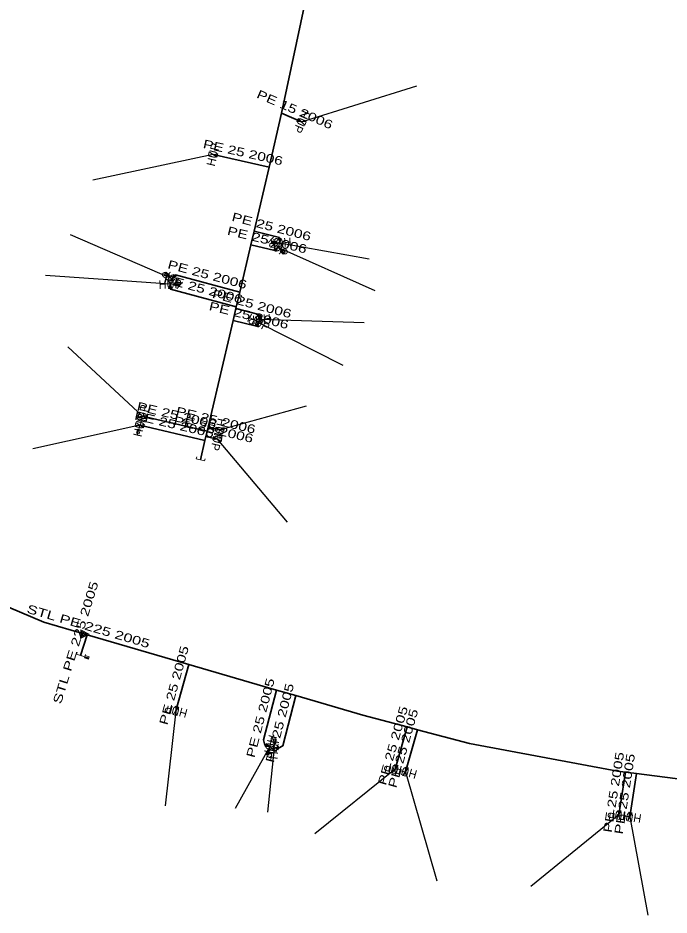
# Model space of a CAD drawing. Extents: x -737484 to -734496, y -1033882 to -1030666.
# Drawn here: x -736493.3 to -736417.8, y -1030969.6 to -1030865.6 of the extents above; entities that cross this region are included whole.
import ezdxf
from ezdxf.enums import TextEntityAlignment as Align

# ---------------------------------------------------------------- set-up
doc = ezdxf.new("R2010")
doc.units = 0
doc.header["$LTSCALE"] = 0.4
for name, color, linetype, lineweight in [('1', 7, 'Continuous', 13), ('22', 7, 'Continuous', 25), ('5', 7, 'Continuous', 35), ('7', 7, 'Continuous', 35)]:
    doc.layers.add(name, color=color, linetype=linetype, lineweight=lineweight)
doc.layers.add('2', color=7, linetype='Continuous')

msp = doc.modelspace()

# ---------------------------------------------------------------- linework, layer by layer
at = {"layer": '1'}
for p, q in [((-736463.478, -1030891.525), (-736463.827, -1030891.5)), ((-736462.91, -1030891.64), (-736463.408, -1030891.605)), ((-736463.14, -1030892.14), (-736462.78, -1030892.487)), ((-736462.778, -1030892.593), (-736462.526, -1030892.836)), ((-736475.822, -1030895.392), (-736476.09, -1030895.167)), ((-736475.43, -1030895.82), (-736475.813, -1030895.498)), ((-736475.64, -1030896.44), (-736475.14, -1030896.422)), ((-736475.062, -1030896.494), (-736474.712, -1030896.482)), ((-736479.372, -1030913.333), (-736479.451, -1030913.674)), ((-736479.17, -1030912.79), (-736479.282, -1030913.277)), ((-736486.03, -1030939.49), (-736485.551, -1030939.636)), ((-736485.502, -1030939.729), (-736485.167, -1030939.832)), ((-736464.07, -1030950.05), (-736464.207, -1030950.53)), ((-736463.58, -1030950.19), (-736463.536, -1030949.691)), ((-736463.455, -1030949.623), (-736463.424, -1030949.275)), ((-736464.3, -1030950.582), (-736464.397, -1030950.918))]:
    msp.add_line(p, q, dxfattribs=at)
for points in [[(-736459.871, -1030877.611), (-736460.027, -1030877.979), (-736460.792, -1030877.22), (-736460.948, -1030877.588)], [(-736471.192, -1030881.492), (-736471.102, -1030881.102), (-736470.217, -1030881.717), (-736470.127, -1030881.327)], [(-736463.907, -1030891.57), (-736463.918, -1030891.719), (-736463.419, -1030891.754), (-736463.408, -1030891.605)], [(-736463.907, -1030891.57), (-736463.897, -1030891.42), (-736463.398, -1030891.455), (-736463.408, -1030891.605)], [(-736463.867, -1030891.535), (-736463.861, -1030891.461), (-736463.437, -1030891.49), (-736463.443, -1030891.565)], [(-736462.936, -1030891.641), (-736462.648, -1030891.919), (-736463.631, -1030892.36), (-736463.343, -1030892.638)], [(-736462.667, -1030892.12), (-736463.065, -1030892.155), (-736462.754, -1030891.124), (-736463.152, -1030891.159)], [(-736462.42, -1030892.834), (-736462.524, -1030892.942), (-736462.884, -1030892.595), (-736462.78, -1030892.487)], [(-736462.473, -1030892.834), (-736462.525, -1030892.888), (-736462.831, -1030892.593), (-736462.779, -1030892.539)], [(-736462.42, -1030892.834), (-736462.316, -1030892.726), (-736462.676, -1030892.379), (-736462.78, -1030892.487)], [(-736476.196, -1030895.177), (-736476.099, -1030895.062), (-736475.716, -1030895.383), (-736475.813, -1030895.498)], [(-736476.196, -1030895.177), (-736476.292, -1030895.292), (-736475.909, -1030895.613), (-736475.813, -1030895.498)], [(-736476.143, -1030895.173), (-736476.094, -1030895.115), (-736475.769, -1030895.389), (-736475.817, -1030895.446)], [(-736475.598, -1030896.331), (-736475.904, -1030896.074), (-736474.955, -1030895.565), (-736475.261, -1030895.308)], [(-736475.857, -1030895.947), (-736475.457, -1030895.933), (-736475.822, -1030896.946), (-736475.422, -1030896.932)], [(-736474.64, -1030896.405), (-736474.645, -1030896.255), (-736475.145, -1030896.272), (-736475.14, -1030896.422)], [(-736474.64, -1030896.405), (-736474.635, -1030896.555), (-736475.135, -1030896.572), (-736475.14, -1030896.422)], [(-736474.677, -1030896.443), (-736474.674, -1030896.518), (-736475.099, -1030896.533), (-736475.102, -1030896.458)], [(-736465.038, -1030900.986), (-736465.436, -1030901.028), (-736465.143, -1030899.991), (-736465.541, -1030900.033)], [(-736465.331, -1030900.354), (-736464.978, -1030900.542), (-736465.801, -1030901.237), (-736465.448, -1030901.425)], [(-736479.372, -1030911.812), (-736479.282, -1030911.422), (-736478.397, -1030912.037), (-736478.307, -1030911.647)], [(-736479.702, -1030912.872), (-736479.612, -1030912.482), (-736478.727, -1030913.097), (-736478.637, -1030912.707)], [(-736479.394, -1030913.764), (-736479.541, -1030913.73), (-736479.428, -1030913.243), (-736479.282, -1030913.277)], [(-736479.422, -1030913.719), (-736479.495, -1030913.702), (-736479.399, -1030913.288), (-736479.326, -1030913.304)], [(-736479.394, -1030913.764), (-736479.248, -1030913.798), (-736479.136, -1030913.31), (-736479.282, -1030913.277)], [(-736469.377, -1030913.257), (-736469.467, -1030913.647), (-736470.352, -1030913.032), (-736470.442, -1030913.422)], [(-736469.647, -1030914.327), (-736469.737, -1030914.717), (-736470.622, -1030914.102), (-736470.712, -1030914.492)], [(-736486.021, -1030936.521), (-736486.038, -1030937.521), (-736485.03, -1030937.038)], [(-736485.935, -1030937.36), (-736485.254, -1030937.034), (-736485.924, -1030936.685)], [(-736485.477, -1030937.03), (-736485.826, -1030936.848), (-736485.833, -1030937.201)], [(-736485.073, -1030939.782), (-736485.117, -1030939.925), (-736485.595, -1030939.779), (-736485.551, -1030939.636)], [(-736485.073, -1030939.782), (-736485.029, -1030939.638), (-736485.507, -1030939.492), (-736485.551, -1030939.636)], [(-736485.12, -1030939.806), (-736485.142, -1030939.878), (-736485.549, -1030939.754), (-736485.527, -1030939.682)], [(-736474.916, -1030946.444), (-736475.302, -1030946.341), (-736474.657, -1030945.478), (-736475.043, -1030945.375)], [(-736463.534, -1030949.995), (-736463.644, -1030950.38), (-736464.495, -1030949.719), (-736464.605, -1030950.104)], [(-736464.095, -1030950.345), (-736464.06, -1030949.947), (-736463.099, -1030950.432), (-736463.064, -1030950.034)], [(-736463.492, -1030949.193), (-736463.642, -1030949.18), (-736463.685, -1030949.678), (-736463.536, -1030949.691)], [(-736463.492, -1030949.193), (-736463.343, -1030949.206), (-736463.386, -1030949.704), (-736463.536, -1030949.691)], [(-736463.459, -1030949.234), (-736463.384, -1030949.241), (-736463.421, -1030949.664), (-736463.496, -1030949.658)], [(-736464.345, -1030951.011), (-736464.489, -1030950.969), (-736464.352, -1030950.489), (-736464.207, -1030950.53)], [(-736464.37, -1030950.964), (-736464.442, -1030950.943), (-736464.325, -1030950.535), (-736464.253, -1030950.555)], [(-736464.345, -1030951.011), (-736464.201, -1030951.052), (-736464.063, -1030950.571), (-736464.207, -1030950.53)], [(-736449.485, -1030953.205), (-736449.87, -1030953.095), (-736449.209, -1030952.244), (-736449.594, -1030952.134)], [(-736448.285, -1030953.505), (-736448.67, -1030953.395), (-736448.009, -1030952.544), (-736448.394, -1030952.434)], [(-736423.47, -1030958.515), (-736423.865, -1030958.452), (-736423.314, -1030957.527), (-736423.709, -1030957.464)], [(-736422.19, -1030958.735), (-736422.585, -1030958.672), (-736422.034, -1030957.747), (-736422.429, -1030957.684)]]:
    msp.add_lwpolyline(points, close=True, dxfattribs=at)
for points in [[(-736471.596, -1030916.678), (-736471.652, -1030916.922), (-736472.627, -1030916.697), (-736472.57, -1030916.453)], [(-736485.478, -1030939.397), (-736485.551, -1030939.636), (-736486.508, -1030939.343), (-736486.435, -1030939.104)]]:
    msp.add_lwpolyline(points, dxfattribs=at)
at = {"layer": '22'}
for p, q in [((-736460.41, -1030877.6), (-736447.011, -1030873.444)), ((-736470.66, -1030881.41), (-736484.603, -1030884.39)), ((-736475.43, -1030895.82), (-736487.21, -1030890.722)), ((-736462.91, -1030891.64), (-736452.549, -1030893.51)), ((-736463.14, -1030892.14), (-736451.906, -1030897.157)), ((-736475.64, -1030896.44), (-736490.106, -1030895.421)), ((-736465.39, -1030900.89), (-736455.627, -1030905.839)), ((-736465.29, -1030900.51), (-736453.146, -1030900.878)), ((-736478.84, -1030911.73), (-736487.532, -1030903.694)), ((-736469.91, -1030913.34), (-736459.844, -1030910.552)), ((-736479.17, -1030912.79), (-736491.594, -1030915.513)), ((-736470.18, -1030914.41), (-736462.055, -1030924.034)), ((-736474.98, -1030945.91), (-736476.215, -1030956.938)), ((-736464.07, -1030950.05), (-736468.094, -1030957.239)), ((-736463.58, -1030950.19), (-736464.37, -1030957.684)), ((-736449.54, -1030952.67), (-736458.851, -1030960.162)), ((-736448.34, -1030952.97), (-736444.712, -1030965.62)), ((-736423.59, -1030957.99), (-736433.796, -1030966.304)), ((-736422.31, -1030958.21), (-736420.21, -1030969.598))]:
    msp.add_line(p, q, dxfattribs=at)
at = {"layer": '5'}
for p, q in [((-736485.29, -1030937.1), (-736486.03, -1030939.49)), ((-736485.53, -1030937.03), (-736485.29, -1030937.1))]:
    msp.add_line(p, q, dxfattribs=at)
for points in [[(-736459.87, -1030863.16), (-736462.74, -1030876.6), (-736464.15, -1030882.86), (-736465.9, -1030890.28), (-736466.27, -1030891.88), (-736467.56, -1030897.36), (-736467.97, -1030899.07), (-736468.01, -1030899.26), (-736468.34, -1030900.64), (-736471.25, -1030913.02), (-736471.36, -1030913.49), (-736471.5, -1030914.1), (-736471.61, -1030914.56), (-736472.14, -1030916.81)], [(-736626.82, -1030914.15), (-736612.8, -1030915.02), (-736591.79, -1030915.58), (-736586.6, -1030916.06), (-736561.2, -1030919.34), (-736536.83, -1030924.14), (-736524.9, -1030926.49), (-736511.55, -1030929.45), (-736508.34, -1030930.09), (-736507.5, -1030930.29), (-736494.4, -1030933.9), (-736490.29, -1030935.64), (-736485.53, -1030937.03)], [(-736485.29, -1030937.1), (-736473.49, -1030940.53), (-736463.3, -1030943.5), (-736461.07, -1030944.15), (-736453.3, -1030946.41), (-736448.15, -1030947.78), (-736446.96, -1030948.1), (-736440.91, -1030949.71), (-736423.75, -1030952.91), (-736422.81, -1030953.03), (-736421.54, -1030953.19), (-736406.57, -1030955.11), (-736404.29, -1030955.41), (-736389.44, -1030957.31), (-736387.69, -1030957.54), (-736373.18, -1030959.4), (-736362.06, -1030960.72), (-736360.97, -1030960.85), (-736346.01, -1030962.62), (-736343.72, -1030962.89), (-736336.57, -1030963.74)]]:
    msp.add_lwpolyline(points, dxfattribs=at)
at = {"layer": '7'}
for p, q in [((-736462.74, -1030876.6), (-736460.41, -1030877.6)), ((-736464.15, -1030882.86), (-736470.66, -1030881.41)), ((-736471.36, -1030913.49), (-736478.84, -1030911.73)), ((-736471.61, -1030914.56), (-736479.17, -1030912.79)), ((-736471.25, -1030913.02), (-736469.91, -1030913.34)), ((-736471.5, -1030914.1), (-736470.18, -1030914.41)), ((-736473.49, -1030940.53), (-736474.98, -1030945.91)), ((-736448.15, -1030947.78), (-736449.54, -1030952.67)), ((-736446.96, -1030948.1), (-736448.34, -1030952.97)), ((-736422.81, -1030953.03), (-736423.59, -1030957.99)), ((-736421.54, -1030953.19), (-736422.31, -1030958.21))]:
    msp.add_line(p, q, dxfattribs=at)
for points in [[(-736465.9, -1030890.28), (-736462.96, -1030891.04), (-736462.91, -1030891.64)], [(-736466.27, -1030891.88), (-736463.52, -1030892.54), (-736463.14, -1030892.14)], [(-736467.56, -1030897.36), (-736475.04, -1030895.36), (-736475.43, -1030895.82)], [(-736467.97, -1030899.07), (-736475.62, -1030897), (-736475.64, -1030896.44)], [(-736468.01, -1030899.26), (-736465.35, -1030899.96), (-736465.29, -1030900.51)], [(-736468.34, -1030900.64), (-736465.61, -1030901.3), (-736465.39, -1030900.89)], [(-736463.3, -1030943.5), (-736464.8, -1030949.29), (-736464.65, -1030949.88), (-736464.07, -1030950.05)], [(-736461.07, -1030944.15), (-736462.59, -1030949.97), (-736463.08, -1030950.23), (-736463.58, -1030950.19)]]:
    msp.add_lwpolyline(points, dxfattribs=at)

# ---------------------------------------------------------------- texts
at = {"layer": '2', "width": 0.95}
for rotation, p in [(247, (-736460.8693, -1030877.4041)), (77, (-736470.1725, -1030881.522)), (316, (-736463.4868, -1030892.4994)), (185, (-736462.9529, -1030891.1417)), (140, (-736475.1081, -1030895.4364)), (2, (-736475.6219, -1030896.9387)), (332, (-736465.6242, -1030901.331)), (186, (-736465.3412, -1030900.0127)), (77, (-736478.3525, -1030911.842)), (77, (-736478.6825, -1030912.902)), (257, (-736470.3965, -1030913.227)), (257, (-736470.6665, -1030914.297)), (165, (-736474.8501, -1030945.4267)), (254, (-736464.5498, -1030949.9117)), (85, (-736463.0813, -1030950.2331)), (164, (-736449.4017, -1030952.1892)), (164, (-736448.2017, -1030952.4892)), (171, (-736423.5113, -1030957.4955)), (171, (-736422.2313, -1030957.7155))]:
    msp.add_text('HUP', height=1, rotation=rotation, dxfattribs=at).set_placement(p, align=Align.CENTER)
at = {"layer": '5', "width": 1.4}
for rotation, p in [(72.796, (-736486.137, -1030938.1464)), (343.74, (-736485.2695, -1030936.584))]:
    msp.add_text('STL PE 225 2005', height=1, rotation=rotation, dxfattribs=at).set_placement(p, align=Align.CENTER)
at = {"layer": '7', "width": 1.35}
for s, rotation, p in [('PE 15 2006', 336.772, (-736461.3772, -1030876.6396)), ('PE 25 2006', 347.443, (-736467.2957, -1030881.6464)), ('PE 25 2006', 345.506, (-736464.0126, -1030890.2511)), ('PE 25 2006', 346.504, (-736464.5097, -1030891.7879)), ('PE 25 2006', 345.03, (-736471.4617, -1030895.7987)), ('PE 25 2006', 344.859, (-736471.9346, -1030897.4785)), ('PE 25 2006', 345.256, (-736466.2847, -1030899.1964)), ('PE 25 2006', 346.409, (-736466.6305, -1030900.5377)), ('PE 25 2006', 346.759, (-736474.985, -1030912.1231)), ('PE 25 2006', 346.569, (-736470.4631, -1030912.6937)), ('PE 25 2006', 346.823, (-736475.2755, -1030913.188)), ('PE 25 2006', 346.784, (-736470.7253, -1030913.7681)), ('PE 25 2005', 74.52, (-736474.7161, -1030943.086)), ('PE 25 2005', 75.476, (-736464.6855, -1030946.8564)), ('PE 25 2005', 75.363, (-736462.4464, -1030947.4438)), ('PE 25 2005', 74.132, (-736449.3258, -1030950.0877)), ('PE 25 2005', 74.179, (-736448.1306, -1030950.3978)), ('PE 25 2005', 81.063, (-736423.6935, -1030955.4322)), ('PE 25 2005', 81.28, (-736422.4185, -1030955.6238))]:
    msp.add_text(s, height=1, rotation=rotation, dxfattribs=at).set_placement(p, align=Align.CENTER)

doc.saveas('drawing.dxf')
